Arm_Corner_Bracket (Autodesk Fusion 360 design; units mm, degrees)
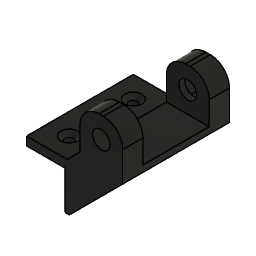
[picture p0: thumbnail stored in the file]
sketch "Sketch1" plane through (0, 0, 0) normal (0, 0, 1) x axis (1, 0, 0)
  line L1 (45, 0) -> (0, 0)
  line L2 (45, 50) -> (45, 0)
  line L3 (0, 50) -> (45, 50)
  line L4 (0, 0) -> (0, 50)
  point P1 (0, 0)
  point P2 (0, 0)
  point P4 (45, 50)
  point P5 (0, 50)
  point P3 (45, 0)
  horizontal L1
  vertical L2
  horizontal L3
  vertical L4
  coincident P1 P2
  dimension "d1" distance P4 P5 = 45
  dimension "d2" distance P3 P4 = 50
extrude "Extrude1" new body sketch "Sketch1" along normal blind 4
sketch "Sketch2" plane through (0, 0, 4) normal (0, 0, 1) x axis (-1, 0, 0)
  line L1 (0, 0) -> (0, -50)
  line L2 (-45, 0) -> (0, 0)
  line L3 (-45, -50) -> (-45, 0)
  line L4 (0, -50) -> (-45, -50)
  circle C1 centre (-10, -40) radius 2
  circle C2 centre (-10, -10) radius 2
  point P6 (-10, -40)
  point P7 (-10, -10)
  dimension "d5" diameter C1 = 4
  dimension "d6" diameter C2 = 4
  dimension "d7" distance L1 P6 = 10
  dimension "d8" distance L4 P6 = 10
  dimension "d9" distance L1 P7 = 10
  dimension "d10" distance L2 P7 = 10
extrude "Extrude2" cut sketch "Sketch2" profile of C1 C2 against normal blind 4
chamfer "Chamfer1" distance 2
sketch "Sketch3" plane through (0, 0, 4) normal (0, 0, 1) x axis (-1, 0, 0)
  line L1 (0, 0) -> (0, -50)
  line L2 (-45, 0) -> (0, 0)
  line L3 (-45, -50) -> (-45, 0)
  line L4 (0, -50) -> (-45, -50)
  line L5 (-25, -50) -> (-45, -50)
  line L6 (-25, 0) -> (-25, -50)
  line L7 (-45, 0) -> (-25, 0)
  line L8 (-45, -50) -> (-45, 0)
  circle C1 centre (-10, -40) radius 4
  circle C2 centre (-10, -10) radius 4
  point P10 (-25, 0)
  point P6 (-45, -50)
  point P8 (-45, -50)
  point P9 (-25, -50)
  horizontal L5
  vertical L6
  horizontal L7
  vertical L8
  coincident L2 P10
  coincident P6 P8
  dimension "d14" distance P8 P9 = 20
extrude "Extrude3" add sketch "Sketch3" profile of L2 L3 L4 L5 L6 L7 L8 along normal blind 6
sketch "Sketch4" plane through (0, 0, 10) normal (0, 0, 1) x axis (-1, 0, 0)
  line L1 (-45, -50) -> (-45, 0)
  line L2 (-25, -50) -> (-45, -50)
  line L3 (-25, 0) -> (-25, -50)
  line L4 (-45, 0) -> (-25, 0)
  line L5 (-25, -50) -> (-45, -50)
  line L6 (-25, -40.5) -> (-25, -50)
  line L7 (-45, -40.5) -> (-25, -40.5)
  line L8 (-45, -50) -> (-45, -40.5)
  line L9 (-25, 0) -> (-45, 0)
  line L10 (-25, -9.5) -> (-25, 0)
  line L11 (-45, -9.5) -> (-25, -9.5)
  line L12 (-45, 0) -> (-45, -9.5)
  point P8 (-25, -40.5)
  point P3 (-45, -50)
  point P6 (-45, -50)
  point P12 (-25, -9.5)
  point P2 (-45, 0)
  point P10 (-45, 0)
  point P9 (-45, -40.5)
  point P13 (-45, -9.5)
  horizontal L5
  vertical L6
  horizontal L7
  vertical L8
  coincident L3 P8
  coincident P3 P6
  horizontal L9
  vertical L10
  horizontal L11
  vertical L12
  coincident L3 P12
  coincident P2 P10
  dimension "d18" distance P6 P9 = 9.5
  dimension "d19" distance P10 P13 = 9.5
  dimension "d20" = 30
extrude "Extrude4" add sketch "Sketch4" along normal blind 20
fillet "Fillet1" radius 9
sketch "Sketch5" plane through (0, 50, 0) normal (0, 1, 0) x axis (-1, 0, 0)
  line L1 (-45, 0) -> (-45, 21)
  line L2 (0, 0) -> (-45, 0)
  line L3 (0, 4) -> (0, 0)
  line L4 (-25, 4) -> (0, 4)
  line L5 (-25, 21) -> (-25, 4)
  line L6 (-36, 30) -> (-34, 30)
  arc A1 centre (-36, 21) radius 9 clockwise from (-45, 21) to (-36, 30)
  arc A2 centre (-34, 21) radius 9 clockwise from (-34, 30) to (-25, 21)
  circle C1 centre (-35, 20) radius 4.1
  point P12 (-35, 20)
  dimension "d24" diameter C1 = 8.2
  dimension "d25" distance L1 P12 = 10
  dimension "d26" distance L6 P12 = 10
extrude "Extrude5" cut sketch "Sketch5" profile of C1 against normal blind 50
sketch "Sketch6" plane through (0, 50, 0) normal (0, 1, 0) x axis (-1, 0, 0)
  line L1 (-45, 0) -> (-45, 21)
  line L2 (0, 0) -> (-45, 0)
  line L3 (0, 4) -> (0, 0)
  line L4 (-25, 4) -> (0, 4)
  line L5 (-25, 21) -> (-25, 4)
  line L6 (-36, 30) -> (-34, 30)
  line L7 (-31.35, 26.3637) -> (-38.65, 26.3637)
  line L8 (-27.7, 20.0417) -> (-31.35, 26.3637)
  line L9 (-31.35, 13.7197) -> (-27.7, 20.0417)
  line L10 (-38.65, 13.7197) -> (-31.35, 13.7197)
  line L11 (-42.3, 20.0417) -> (-38.65, 13.7197)
  line L12 (-38.65, 26.3637) -> (-42.3, 20.0417)
  circle C1 centre (-35, 20) radius 4.1
  arc A1 centre (-36, 21) radius 9 clockwise from (-45, 21) to (-36, 30)
  arc A2 centre (-34, 21) radius 9 clockwise from (-34, 30) to (-25, 21)
  point P13 (-38.65, 26.3637)
  point P14 (-31.35, 26.3637)
  point P15 (-27.7, 20.0417)
  point P16 (-31.35, 13.7197)
  point P17 (-38.65, 13.7197)
  point P18 (-42.3, 20.0417)
  perpendicular L5 L7
  parallel L7 L10
  parallel L8 L11
  dimension "d29" angle L7 L12 = 120
  dimension "d30" angle L7 L8 = 120
  dimension "d31" angle L8 L9 = 120
  dimension "d32" angle L9 L10 = 120
  dimension "d33" angle L10 L11 = 120
  dimension "d34" angle L11 L12 = 120
  dimension "d36" distance P13 P14 = 7.3
  dimension "d37" distance P14 P15 = 7.3
  dimension "d38" distance P15 P16 = 7.3
  dimension "d39" distance P16 P17 = 7.3
  dimension "d40" = 7
  dimension "d41" = 7
  dimension "d42" distance L1 P18 = 2.7
  dimension "d43" = 3.4551
extrude "Extrude6" cut sketch "Sketch6" profile of C1 L7 L8 L9 L10 L11 L12 against normal blind 6.7
sketch "Sketch7" plane through (0, 0, 0) normal (0, 0, -1) x axis (1, 0, 0)
  line L1 (0, -50) -> (0, 0)
  line L2 (45, -50) -> (0, -50)
  line L3 (45, 0) -> (45, -50)
  line L4 (0, 0) -> (45, 0)
  line L5 (18, 0) -> (45, 0)
  line L6 (18, -50) -> (18, 0)
  line L7 (45, -50) -> (18, -50)
  line L8 (45, 0) -> (45, -50)
  circle C1 centre (10, -40) radius 2
  circle C2 centre (10, -10) radius 2
  point P10 (18, -50)
  point P7 (45, 0)
  point P8 (45, 0)
  horizontal L5
  vertical L6
  horizontal L7
  vertical L8
  coincident L2 P10
  coincident P7 P8
  dimension "d46" distance L1 L6 = 18
extrude "Extrude7" add sketch "Sketch7" profile of L2 L3 L4 L5 L6 L7 L8 along normal blind 18
chamfer "Chamfer2" distance 25
chamfer "Chamfer3" distance 6
sketch "Sketch8" plane through (18, 0, 0) normal (-1, 0, 0) x axis (0, -1, 0)
  line L1 (-50, 0) -> (0, 0)
  line L2 (-50, -18) -> (-50, 0)
  line L3 (0, -18) -> (-50, -18)
  line L4 (0, 0) -> (0, -18)
  circle C1 centre (-25, -9) radius 2
  point P6 (-25, -9)
  dimension "d51" diameter C1 = 4
  dimension "d52" distance L2 P6 = 25
  dimension "d53" distance L3 P6 = 9
extrude "Extrude8" cut sketch "Sketch8" profile of C1 against normal blind 18
sketch "Sketch9" plane through (45, 0, 0) normal (1, 0, 0) x axis (0, 1, 0)
  line L1 (50, 7) -> (0, 7)
  line L2 (50, 21) -> (50, 7)
  line L3 (40.5, 21) -> (50, 21)
  line L4 (40.5, 10) -> (40.5, 21)
  line L5 (9.5, 10) -> (40.5, 10)
  line L6 (9.5, 21) -> (9.5, 10)
  line L7 (0, 21) -> (9.5, 21)
  line L8 (0, 7) -> (0, 21)
  circle C1 centre (25, -9) radius 3.5
  dimension "d58" diameter C1 = 7
extrude "Extrude9" cut sketch "Sketch9" profile of C1 against normal blind 19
